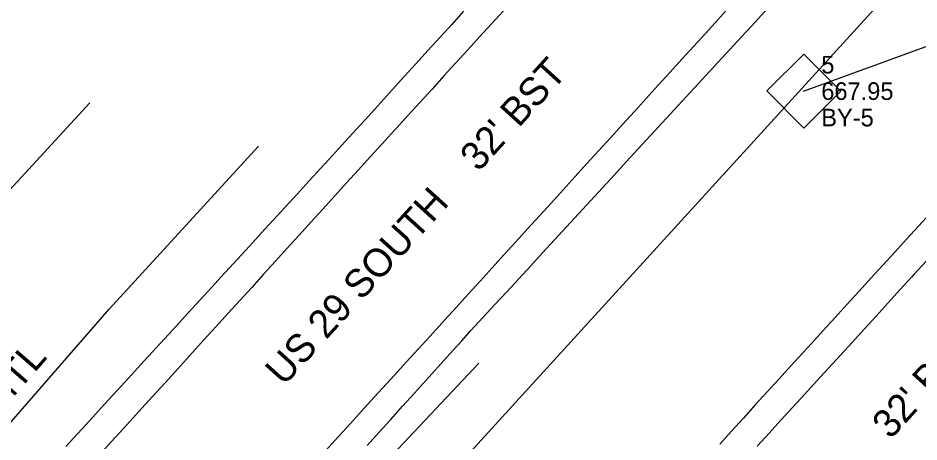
# Model space of a CAD drawing. Extents: x 1806071 to 1809844, y 912722 to 917035.
# Drawn here: x 1809158.4 to 1809286, y 916181.4 to 916241.5 of the extents above; entities that cross this region are included whole.
import ezdxf

# ---------------------------------------------------------------- set-up
doc = ezdxf.new("R2010")
doc.units = 0
for name, color, linetype in [('CTL Supplemental Horizontal and Vertical CELL', 7, 'Continuous'), ('CTL Supplemental Horizontal and Vertical Cogo Comment', 7, 'Continuous'), ('CTL Supplemental Horizontal and Vertical Cogo Elevation', 7, 'Continuous'), ('CTL Supplemental Horizontal and Vertical Cogo Number', 7, 'Continuous'), ('Exist Guardrail', 7, 'Continuous'), ('Exist Guardrail Text', 7, 'Continuous'), ('Exist Horizontal Alignment', 7, 'Continuous'), ('Exist Horizontal Alignment Station Label', 7, 'Continuous'), ('Exist Roads EOP', 7, 'Continuous'), ('Exist Roads EOP Text', 7, 'Continuous'), ('Exist Roads EOT', 7, 'Continuous'), ('Exist Vegetation Woods Line', 7, 'Continuous')]:
    doc.layers.add(name, color=color, linetype=linetype)

msp = doc.modelspace()

# ---------------------------------------------------------------- linework, layer by layer
at = {"layer": 'CTL Supplemental Horizontal and Vertical CELL'}
msp.add_line((1809269.67, 916231.14), (1809269.67, 916231.14), dxfattribs=at)
msp.add_lwpolyline([(1809264.45, 916231.16), (1809269.69, 916236.4), (1809274.94, 916231.15), (1809269.7, 916225.91)], close=True, dxfattribs=at)
at = {"layer": 'Exist Guardrail'}
for points in [[(1809118.47, 916138.61), (1809130.79, 916152.66), (1809150.8, 916176.67), (1809171.3, 916200.24), (1809192.48, 916223.35)], [(1809223.66, 916192.6), (1809202.38, 916169.96), (1809189.69, 916156.01), (1809176.75, 916142.41), (1809163.93, 916128.69)]]:
    msp.add_lwpolyline(points, dxfattribs=at)
at = {"layer": 'Exist Horizontal Alignment'}
msp.add_line((1806073.69, 912724.84), (1809374.2, 916346.52), dxfattribs=at)
at = {"layer": 'Exist Horizontal Alignment Station Label'}
msp.add_line((1809269.67, 916231.14), (1809290.09, 916238.61), dxfattribs=at)
at = {"layer": 'Exist Roads EOP'}
for points in [[(1809207.85, 916180.9), (1809209.52, 916182.76), (1809211.2, 916184.61), (1809212.88, 916186.47), (1809214.55, 916188.33), (1809216.23, 916190.18), (1809217.9, 916192.04), (1809219.58, 916193.89), (1809221.25, 916195.75), (1809222.56, 916197.19), (1809224.25, 916199.03), (1809225.94, 916200.87), (1809227.63, 916202.71), (1809229.33, 916204.55), (1809231.02, 916206.39), (1809232.71, 916208.23), (1809234.4, 916210.07), (1809236.1, 916211.91), (1809237.79, 916213.75), (1809239.48, 916215.59), (1809241.17, 916217.43), (1809242.87, 916219.27), (1809244.56, 916221.11), (1809246.25, 916222.95), (1809247.95, 916224.79), (1809249.64, 916226.63), (1809251.33, 916228.47), (1809253.02, 916230.31), (1809254.72, 916232.15), (1809256.41, 916233.99), (1809258.1, 916235.83), (1809259.79, 916237.67), (1809261.49, 916239.51), (1809262.84, 916240.98), (1809264.53, 916242.82)], [(1809221.51, 916242.45), (1809219.83, 916240.6), (1809218.15, 916238.75), (1809216.47, 916236.9), (1809214.79, 916235.05), (1809213.11, 916233.2), (1809211.43, 916231.35), (1809209.75, 916229.5), (1809208.07, 916227.65), (1809206.39, 916225.8), (1809204.69, 916223.93), (1809203, 916222.08), (1809201.31, 916220.24), (1809199.62, 916218.4), (1809197.93, 916216.55), (1809196.24, 916214.71), (1809194.55, 916212.87), (1809192.86, 916211.02), (1809191.18, 916209.18), (1809189.49, 916207.34), (1809187.8, 916205.49), (1809187.58, 916205.25), (1809185.89, 916203.41), (1809184.2, 916201.56), (1809182.51, 916199.72), (1809180.83, 916197.87), (1809179.14, 916196.03), (1809177.45, 916194.18), (1809175.76, 916192.34), (1809174.08, 916190.5), (1809172.39, 916188.65), (1809170.7, 916186.81), (1809170.25, 916186.31), (1809168.56, 916184.47), (1809166.88, 916182.62), (1809165.19, 916180.78)], [(1809287.63, 916213.85), (1809285.94, 916212), (1809284.26, 916210.15), (1809282.57, 916208.31), (1809280.89, 916206.46), (1809279.2, 916204.61), (1809277.52, 916202.77), (1809275.83, 916200.92), (1809274.15, 916199.07), (1809272.46, 916197.22), (1809270.78, 916195.38), (1809269.56, 916194.04), (1809267.88, 916192.19), (1809266.19, 916190.35), (1809264.51, 916188.5), (1809262.83, 916186.65), (1809261.15, 916184.8), (1809259.46, 916182.95), (1809257.78, 916181.1)]]:
    msp.add_lwpolyline(points, dxfattribs=at)
at = {"layer": 'Exist Roads EOT'}
for points in [[(1809201.62, 916179.78), (1809203.3, 916181.63), (1809204.99, 916183.48), (1809206.67, 916185.33), (1809208.35, 916187.18), (1809210.04, 916189.03), (1809211.72, 916190.87), (1809213.4, 916192.72), (1809215.09, 916194.57), (1809216.77, 916196.42), (1809218.45, 916198.27), (1809218.81, 916198.67), (1809220.5, 916200.52), (1809222.18, 916202.37), (1809223.86, 916204.22), (1809225.54, 916206.07), (1809227.22, 916207.92), (1809228.9, 916209.77), (1809230.58, 916211.62), (1809232.26, 916213.47), (1809233.95, 916215.32), (1809235.63, 916217.17), (1809237.31, 916219.02), (1809238.99, 916220.87), (1809240.67, 916222.72), (1809242.35, 916224.57), (1809244.03, 916226.42), (1809245.72, 916228.27), (1809247.4, 916230.12), (1809249.08, 916231.97), (1809250.76, 916233.82), (1809252.44, 916235.67), (1809254.12, 916237.52), (1809255.8, 916239.37), (1809257.48, 916241.22), (1809259.17, 916243.07)], [(1809227.16, 916242.52), (1809225.47, 916240.67), (1809223.78, 916238.83), (1809222.1, 916236.98), (1809220.41, 916235.13), (1809218.73, 916233.29), (1809217.04, 916231.44), (1809215.36, 916229.59), (1809213.67, 916227.75), (1809211.99, 916225.9), (1809211.66, 916225.54), (1809209.98, 916223.69), (1809208.3, 916221.84), (1809206.62, 916219.99), (1809204.94, 916218.14), (1809203.26, 916216.29), (1809201.58, 916214.43), (1809199.9, 916212.58), (1809198.22, 916210.73), (1809196.54, 916208.88), (1809194.86, 916207.03), (1809193.18, 916205.18), (1809191.5, 916203.32), (1809189.82, 916201.47), (1809188.14, 916199.62), (1809186.47, 916197.77), (1809184.79, 916195.92), (1809183.11, 916194.07), (1809181.43, 916192.21), (1809179.75, 916190.36), (1809178.07, 916188.51), (1809176.39, 916186.66), (1809174.71, 916184.81), (1809173.3, 916183.26), (1809171.62, 916181.42), (1809169.93, 916179.58)], [(1809287.03, 916207.03), (1809285.34, 916205.18), (1809285, 916204.8), (1809283.31, 916202.95), (1809281.63, 916201.11), (1809279.94, 916199.26), (1809278.25, 916197.41), (1809276.57, 916195.57), (1809274.88, 916193.72), (1809273.2, 916191.88), (1809271.51, 916190.03), (1809269.82, 916188.18), (1809268.14, 916186.34), (1809266.45, 916184.49), (1809264.77, 916182.65), (1809263.08, 916180.8)]]:
    msp.add_lwpolyline(points, dxfattribs=at)
at = {"layer": 'Exist Vegetation Woods Line'}
msp.add_lwpolyline([(1809168.58, 916229.47), (1809057.46, 916108.6), (1809022.98, 916100.47), (1808916.26, 916135.27)], dxfattribs=at)

# ---------------------------------------------------------------- texts
at = {"layer": 'CTL Supplemental Horizontal and Vertical Cogo Comment'}
msp.add_text('BY-5', height=2.5, dxfattribs=at).set_placement((1809272.17, 916226.14))
at = {"layer": 'CTL Supplemental Horizontal and Vertical Cogo Elevation'}
msp.add_text('667.95', height=2.5, dxfattribs=at).set_placement((1809272.17, 916229.89))
at = {"layer": 'CTL Supplemental Horizontal and Vertical Cogo Number'}
msp.add_text('5', height=2.5, dxfattribs=at).set_placement((1809272.17, 916233.64))
at = {"layer": 'Exist Guardrail Text'}
msp.add_text('MTL', height=4, rotation=48.9805, dxfattribs=at).set_placement((1809155.65, 916185.29))
at = {"layer": 'Exist Roads EOP Text'}
for s, rotation, p in [("US 29 SOUTH    32' BST", 47.75, (1809196.05, 916189.22)), ("US 29 NORTH    32' BST", 47.6886, (1809254.17, 916151.11))]:
    msp.add_text(s, height=4, rotation=rotation, dxfattribs=at).set_placement(p)

doc.saveas('drawing.dxf')
